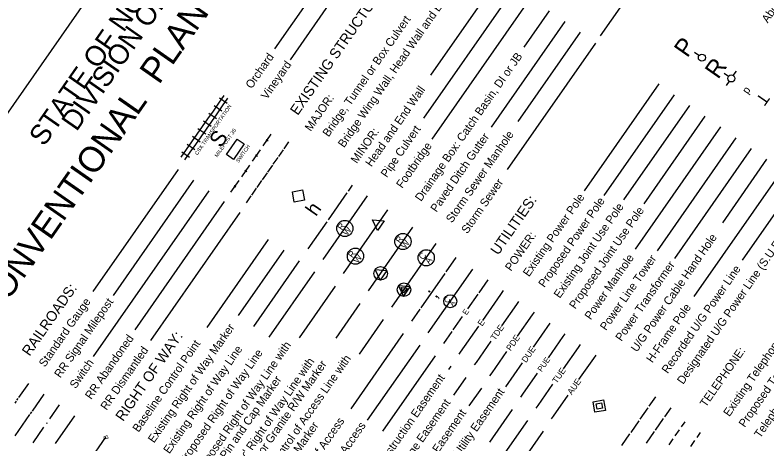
# Model space of a CAD drawing. Extents: x 1731327 to 1735374, y 884856 to 889832.
# Drawn here: x 1733952 to 1734752, y 888724 to 889180 of the extents above; entities that cross this region are included whole.
import ezdxf

# ---------------------------------------------------------------- set-up
doc = ezdxf.new("R2010")
doc.units = 0
for name, color, linetype in [('Exist Building', 7, 'Continuous'), ('Exist Roads EOP Other', 7, 'Continuous'), ('Exist Structure Major Deck Tunnel Box Culvert Text', 7, 'Continuous'), ('Exist Utilities Telephone Pole CELL', 7, 'Continuous'), ('Exist Vegetation Woods Line', 7, 'Continuous')]:
    doc.layers.add(name, color=color, linetype=linetype)

msp = doc.modelspace()

# ---------------------------------------------------------------- linework, layer by layer
at = {"layer": 'Exist Building'}
for p, q in [((1734503.78, 888826.4), (1734521.63, 888851.98)), ((1734474.42, 888784.34), (1734492.33, 888810))]:
    msp.add_line(p, q, dxfattribs=at)
at = {"layer": 'Exist Roads EOP Other'}
msp.add_line((1734573.85, 888763.9), (1734573.85, 888763.9), dxfattribs=at)
for points in [[(1734567.25, 888768.51), (1734578.46, 888770.5), (1734580.45, 888759.29), (1734569.24, 888757.3)], [(1734570.55, 888766.2), (1734576.15, 888767.2), (1734577.15, 888761.6), (1734571.55, 888760.6)]]:
    msp.add_lwpolyline(points, close=True, dxfattribs=at)
at = {"layer": 'Exist Structure Major Deck Tunnel Box Culvert Text'}
msp.add_lwpolyline([(1734249.24, 888980.89), (1734247.31, 888991.77), (1734258.2, 888993.71), (1734260.13, 888982.82)], close=True, dxfattribs=at)
at = {"layer": 'Exist Utilities Telephone Pole CELL'}
msp.add_lwpolyline([(1734410.98, 887822.38), (1735374.4, 889202.95), (1734472.34, 889832.45), (1733508.91, 888451.88)], close=True, dxfattribs=at)
msp.add_lwpolyline([(1734410.98, 887822.38), (1735374.4, 889202.95), (1734472.34, 889832.45), (1733508.91, 888451.88)], close=True, dxfattribs=at)
at = {"layer": 'Exist Vegetation Woods Line'}
for p, q in [((1734345.68, 889311.65), (1734228.43, 889143.63)), ((1734362.08, 889300.21), (1734244.83, 889132.18)), ((1734467.87, 889221.13), (1734394.46, 889115.94)), ((1734484.26, 889209.68), (1734386.89, 889070.15)), ((1734500.66, 889198.24), (1734395.69, 889047.81)), ((1734520.69, 889184.26), (1734493.69, 889145.56)), ((1734575.21, 889157.56), (1734598.39, 889190.79)), ((1734537.09, 889172.82), (1734458.73, 889060.54)), ((1734553.49, 889161.38), (1734487.3, 889066.54)), ((1734569.89, 889149.93), (1734475.94, 889015.31)), ((1734679.9, 889136.57), (1734675.29, 889139.79)), ((1734716.44, 889115.38), (1734719.66, 889120)), ((1734711.22, 889114.46), (1734706.61, 889117.67)), ((1734637.07, 889106.45), (1734557.71, 888992.73)), ((1734712.15, 889109.24), (1734708.93, 889104.62)), ((1734168.99, 889085.87), (1734174.71, 889094.07)), ((1734178, 889085.68), (1734169.8, 889091.4)), ((1734173.09, 889083.01), (1734178.81, 889091.21)), ((1734653.47, 889095), (1734578.57, 888987.67)), ((1734163.27, 889077.67), (1734168.99, 889085.87)), ((1734172.28, 889077.48), (1734164.08, 889083.2)), ((1734167.37, 889074.81), (1734173.09, 889083.01)), ((1734669.87, 889083.56), (1734599.77, 888983.11)), ((1734157.55, 889069.47), (1734163.27, 889077.67)), ((1734166.56, 889069.28), (1734158.36, 889075)), ((1734161.65, 889066.61), (1734167.37, 889074.81)), ((1734686.27, 889072.12), (1734621.32, 888979.05)), ((1734151.83, 889061.28), (1734157.55, 889069.47)), ((1734160.84, 889061.08), (1734152.64, 889066.81)), ((1734155.93, 889058.41), (1734161.65, 889066.61)), ((1734146.11, 889053.08), (1734151.83, 889061.28)), ((1734155.12, 889052.88), (1734146.92, 889058.61)), ((1734150.21, 889050.22), (1734155.93, 889058.41)), ((1734702.66, 889060.67), (1734611.98, 888930.72)), ((1734140.38, 889044.88), (1734146.11, 889053.08)), ((1734149.39, 889044.69), (1734141.2, 889050.41)), ((1734144.48, 889042.02), (1734150.21, 889050.22)), ((1734216.37, 889040.62), (1734224.95, 889052.92)), ((1734219.64, 889047.48), (1734221.69, 889046.05)), ((1734719.06, 889049.23), (1734635.24, 888929.12)), ((1734134.66, 889036.68), (1734140.38, 889044.88)), ((1734143.67, 889036.49), (1734135.47, 889042.21)), ((1734138.76, 889033.82), (1734144.48, 889042.02)), ((1734238.49, 889037.37), (1734243.64, 889044.75)), ((1734128.94, 889028.48), (1734134.66, 889036.68)), ((1734137.95, 889028.29), (1734129.75, 889034.01)), ((1734133.04, 889025.62), (1734138.76, 889033.82)), ((1734204.93, 889024.22), (1734213.51, 889036.52)), ((1734232.77, 889029.18), (1734237.92, 889036.55)), ((1734735.46, 889037.79), (1734653.7, 888920.63)), ((1734208.19, 889031.09), (1734210.24, 889029.66)), ((1734227.05, 889020.98), (1734232.19, 889028.36)), ((1734751.86, 889026.35), (1734704.75, 888958.85)), ((1734125.76, 889015.59), (1734035.12, 888885.71)), ((1734193.48, 889007.82), (1734202.07, 889020.12)), ((1734221.32, 889012.78), (1734226.47, 889020.16)), ((1734196.75, 889014.69), (1734198.8, 889013.26)), ((1734215.6, 889004.58), (1734220.75, 889011.96)), ((1734768.25, 889014.9), (1734674.48, 888880.52)), ((1734142.15, 889004.15), (1734056.59, 888881.54)), ((1734182.04, 888991.43), (1734190.62, 889003.72)), ((1734209.88, 888996.38), (1734215.03, 889003.76)), ((1734784.65, 889003.46), (1734725.74, 888919.04)), ((1734158.55, 888992.71), (1734035.59, 888816.5)), ((1734185.31, 888998.29), (1734187.36, 888996.86)), ((1734204.16, 888988.18), (1734209.31, 888995.56)), ((1734307.09, 888992.55), (1734311.38, 888998.7)), ((1734198.44, 888979.98), (1734203.59, 888987.36)), ((1734280.21, 888919.87), (1734327.41, 888987.51)), ((1734285.63, 888961.8), (1734305.66, 888990.5)), ((1734174.95, 888981.26), (1734079.88, 888845.03)), ((1734191.35, 888969.82), (1734096.28, 888833.59)), ((1734191.35, 888969.82), (1734096.28, 888833.59)), ((1734301.63, 888904.93), (1734348.83, 888972.57)), ((1734264.18, 888931.06), (1734284.2, 888959.75)), ((1734328.27, 888886.33), (1734375.47, 888953.97)), ((1734338.5, 888957.77), (1734338.5, 888957.77)), ((1734221.74, 888941.13), (1734156.39, 888847.49)), ((1734353.07, 888869.03), (1734400.27, 888936.67)), ((1734238.14, 888929.69), (1734189.54, 888860.05)), ((1734411, 888906.47), (1734421.66, 888921.74)), ((1734254.53, 888918.24), (1734205.94, 888848.61)), ((1734270.93, 888906.8), (1734222.33, 888837.16)), ((1734341.26, 888904.94), (1734341.26, 888904.94)), ((1734384.45, 888868.42), (1734409.86, 888904.83)), ((1734391.96, 888841.89), (1734439.16, 888909.53)), ((1734445.98, 888884.36), (1734455.56, 888898.09)), ((1734292.95, 888891.44), (1734254.55, 888836.41)), ((1734366.06, 888887.64), (1734366.06, 888887.64)), ((1734434.11, 888867.35), (1734444.84, 888882.72)), ((1734449.85, 888854.96), (1734469.16, 888882.63)), ((1734469.16, 888882.63), (1734471.96, 888886.64)), ((1734319.21, 888873.11), (1734293.47, 888836.22)), ((1734470.25, 888849.25), (1734485.98, 888871.8)), ((1734485.98, 888871.8), (1734488.36, 888875.2)), ((1734374.45, 888854.1), (1734383.3, 888866.78)), ((1734502.64, 888860.72), (1734504.75, 888863.76)), ((1734344.01, 888855.8), (1734318.48, 888819.22)), ((1734418.38, 888844.8), (1734428.39, 888859.15)), ((1734486.9, 888838.18), (1734502.64, 888860.72)), ((1734426.25, 888821.14), (1734445.56, 888848.81)), ((1734365.28, 888840.96), (1734309.47, 888760.98)), ((1734408.36, 888830.44), (1734417.23, 888843.16)), ((1734535.46, 888837.86), (1734537.56, 888840.86)), ((1734443.07, 888810.3), (1734458.8, 888832.85)), ((1734519.73, 888815.31), (1734535.46, 888837.86)), ((1734382.79, 888828.74), (1734326.97, 888748.76)), ((1734535.85, 888803.47), (1734551.58, 888826.02)), ((1734551.58, 888826.02), (1734553.95, 888829.42)), ((1734399.18, 888817.3), (1734343.37, 888737.32)), ((1734424.75, 888819), (1734426.25, 888821.14)), ((1734459.72, 888799.23), (1734475.46, 888821.78)), ((1734567.98, 888814.58), (1734570.35, 888817.98)), ((1734441.15, 888807.56), (1734443.07, 888810.3)), ((1734552.24, 888792.03), (1734567.98, 888814.58)), ((1734415.8, 888806.17), (1734413.41, 888802.75)), ((1734431.98, 888794.42), (1734418.74, 888775.43)), ((1734457.55, 888796.11), (1734459.72, 888799.23)), ((1734492.55, 888776.37), (1734508.28, 888798.92)), ((1733956.36, 888772.85), (1733966.92, 888787.98)), ((1734508.67, 888764.53), (1734524.4, 888787.07)), ((1733970.8, 888758.61), (1733983.31, 888776.53)), ((1734448.38, 888782.97), (1734435.13, 888763.99)), ((1734490.35, 888773.22), (1734492.55, 888776.37)), ((1734525.07, 888753.08), (1734540.8, 888775.63)), ((1733952.35, 888767.11), (1733953.78, 888769.16)), ((1733954.36, 888769.98), (1733955.79, 888772.03)), ((1734627.07, 888763.77), (1734633.94, 888773.61)), ((1733989.41, 888750.33), (1733999.71, 888765.09)), ((1734481.18, 888760.08), (1734457.07, 888725.53)), ((1734506.75, 888761.78), (1734508.67, 888764.53)), ((1734617.35, 888749.83), (1734625.93, 888762.13)), ((1734643.47, 888752.32), (1734650.34, 888762.16)), ((1733952.5, 888732.37), (1733968.23, 888754.92)), ((1733968.8, 888755.74), (1733970.23, 888757.79)), ((1733995.37, 888723.93), (1734016.11, 888753.65)), ((1734523.15, 888750.34), (1734525.07, 888753.08)), ((1733985.98, 888745.41), (1733986.55, 888746.23)), ((1734497.58, 888748.64), (1734473.47, 888714.09)), ((1734607.62, 888735.89), (1734616.2, 888748.19)), ((1734633.74, 888738.39), (1734642.33, 888750.68)), ((1734664.75, 888747.04), (1734661.09, 888741.8)), ((1733971.68, 888724.92), (1733983.12, 888741.31)), ((1734513.98, 888737.19), (1734474.81, 888681.07)), ((1734624.02, 888724.45), (1734632.6, 888736.75)), ((1734658.86, 888738.6), (1734654.36, 888732.16)), ((1734681.15, 888735.6), (1734677.48, 888730.35)), ((1734028.16, 888701.04), (1734048.9, 888730.76)), ((1734597.89, 888721.95), (1734606.47, 888734.25)), ((1734652.25, 888729.13), (1734647.81, 888722.78)), ((1734675.25, 888727.16), (1734670.76, 888720.72))]:
    msp.add_line(p, q, dxfattribs=at)
for points in [[(1734177.1, 889031.45), (1734188.54, 889047.85), (1734196, 889042.64), (1734184.56, 889026.24)], [(1734337.88, 888950.58), (1734332.6, 888961.89), (1734345.03, 888960.83)], [(1734340.64, 888897.76), (1734335.36, 888909.06), (1734347.79, 888908.01)], [(1734365.43, 888880.45), (1734372.59, 888890.7), (1734360.15, 888891.76)], [(1734365.73, 888883.88), (1734362.97, 888889.79), (1734369.47, 888889.24)]]:
    msp.add_lwpolyline(points, close=True, dxfattribs=at)
for centre, radius in [((1734682.98, 889134.43), 3.75), ((1734714.31, 889112.3), 3.75), ((1734303.16, 888952.77), 8.61), ((1734364.94, 888938.88), 8.61), ((1734314.45, 888923.31), 8.61), ((1734389.74, 888921.58), 8.61), ((1734341.26, 888904.94), 7.2), ((1734366.06, 888887.63), 7.2), ((1734415.35, 888875.4), 6.89)]:
    msp.add_circle(centre, radius, dxfattribs=at)

# ---------------------------------------------------------------- texts
at = {"layer": 'Exist Building'}
msp.add_text('DUE', height=6.549, rotation=55.09106, dxfattribs=at).set_placement((1734495.95, 888809.42))
at = {"layer": 'Exist Vegetation Woods Line'}
for s, height, rotation, p in [('CONVENTIONAL  PLAN SHEET SYMBOLS', 27.1947, 55.09106, (1733929.61, 888853.02)), ('STATE OF NORTH CAROLINA', 21.4145, 55.09106, (1733983.25, 889039.08)), ('DIVISION OF HIGHWAYS', 21.4145, 55.09106, (1734017.76, 889055.04)), ('Above Ground Gas Line', 8.7482, 55.09106, (1734753.02, 889170.66)), ('Bridge Wing Wall, Head Wall and End Wall', 8.7482, 55.09106, (1734302.28, 889038.03)), ('EXISTING STRUCTURES:', 10.9977, 55.09106, (1734253.08, 889072.36)), ('Bridge, Tunnel or Box Culvert', 8.7482, 55.09106, (1734285.88, 889049.48)), ('P', 18.75, 55.09106, (1734667.44, 889133.58)), ('Orchard', 8.748, 55.09106, (1734203.97, 889100.68)), ('Drainage Box: Catch Basin, DI or JB', 8.7482, 55.09106, (1734384.26, 888980.83)), ('Vineyard', 8.748, 55.09106, (1734220.37, 889089.23)), ('R', 18.75, 55.09106, (1734700.23, 889110.7)), ('Head and End Wall', 8.7482, 55.09106, (1734331.44, 889017.68)), ('p', 8.25, 55.09106, (1734731.73, 889095.12)), ('MAJOR:', 8.748, 55.09106, (1734266.95, 889055.34)), ('T', 12.5, 235.09108, (1734745.56, 889098.12)), ('CSX TRANSPORTATION', 3.9991, 55.09106, (1734146.41, 889030.39)), ('S', 16.5, 55.09106, (1734171.21, 889037.71)), ('MILEPOST 35', 3.9991, 55.09106, (1734167.47, 889028.11)), ('MINOR:', 8.748, 55.09106, (1734315.89, 889021.18)), ('Pipe Culvert', 8.7482, 55.09106, (1734347.83, 889006.25)), ('Storm Sewer Manhole', 8.7482, 55.09106, (1734417.07, 888957.94)), ('Paved Ditch Gutter', 8.7482, 55.09106, (1734400.67, 888969.38)), ('SWITCH', 3.999, 55.09106, (1734190.2, 889022.25)), ('Footbridge', 8.748, 55.09106, (1734364.23, 888994.81)), ('Storm Sewer', 8.7482, 55.09106, (1734433.47, 888946.5)), ('UTILITIES:', 10.998, 55.09106, (1734466.26, 888923.6)), ('Existing Power Pole', 8.7482, 55.09106, (1734499.05, 888900.73)), ('Proposed Power Pole', 8.7482, 55.09106, (1734515.45, 888889.29)), ('h', 15, 55.09106, (1734272.53, 888964.87)), ('Existing Joint Use Pole', 8.7482, 55.09106, (1734531.83, 888877.85)), ('Proposed Joint Use Pole', 8.7482, 55.09106, (1734548.25, 888866.41)), ('R', 6.75, 55.09106, (1734300.21, 888950.31)), ('W', 6.75, 55.09106, (1734305.85, 888944.5)), ('R', 6.75, 55.09106, (1734361.99, 888936.42)), ('POWER:', 8.748, 55.09106, (1734480.02, 888906.65)), ('U/G Power Cable Hand Hole', 8.7482, 55.09106, (1734613.85, 888820.65)), ('Designated U/G Power Line (S.U.E.*)', 8.7482, 55.09106, (1734663.04, 888786.34)), ('W', 6.75, 55.09106, (1734367.63, 888930.61)), ('R', 6.75, 55.09106, (1734311.5, 888920.85)), ('W', 6.75, 55.09106, (1734317.14, 888915.04)), ('C', 6.75, 55.09106, (1734386.65, 888918.91)), ('A', 6.75, 55.09106, (1734393.13, 888914.31)), ('Power Manhole', 8.7482, 55.09106, (1734564.65, 888854.97)), ('Power Line Tower', 8.7482, 55.09106, (1734581.03, 888843.53)), ('Power Transformer', 8.7482, 55.09106, (1734597.42, 888832.08)), ('Recorded U/G Power Line', 8.7482, 55.09106, (1734646.64, 888797.77)), ('RAILROADS:', 10.998, 55.09106, (1733967.83, 888816.27)), (';', 15, 55.09106, (1734399.91, 888877.48)), ('Standard Gauge', 8.7482, 55.09106, (1733984.05, 888804.62)), ('RR Signal Milepost', 8.7482, 55.09106, (1734000.44, 888793.18)), ('C', 5.4, 55.09106, (1734412.58, 888872.86)), ('A', 5.4, 55.09106, (1734418.21, 888869.59)), ('H-Frame Pole', 8.7482, 55.09106, (1734630.24, 888809.21)), ('E', 6, 55.09106, (1734432.68, 888860.06)), ('E', 6.55, 55.09106, (1734449.18, 888848.24)), ('Existing Telephone Pole', 8.7482, 55.09106, (1734712.23, 888751.99)), ('Existing Right of Way Marker', 8.7482, 55.09106, (1734100.12, 888723.96)), ('TDE', 6.549, 55.09106, (1734463, 888833.1)), ('Proposed Telephone Pole', 8.7482, 55.09106, (1734728.63, 888740.55)), ('RR Abandoned', 8.7482, 55.09106, (1734033.24, 888770.29)), ('RIGHT OF WAY:', 10.9977, 55.09106, (1734067.32, 888746.84)), ('PDE', 6.549, 55.09106, (1734479.59, 888821.94)), ('Baseline Control Point', 8.7482, 55.09106, (1734083.72, 888735.4)), ('Proposed Right of Way Line with', 8.7482, 55.09106, (1734149.31, 888689.63)), ('RR Dismantled', 8.7482, 55.09106, (1734049.64, 888758.85)), ('Existing Right of Way Line', 8.7482, 55.09106, (1734116.51, 888712.51)), ('Proposed Right of Way Line', 8.7482, 55.09106, (1734132.91, 888701.07)), ('TELEPHONE:', 8.748, 55.09106, (1734687.3, 888762)), ('Proposed Control of Access Line with', 8.7482, 55.09106, (1734198.89, 888655.03)), ('PUE', 5.999, 55.09106, (1734512.52, 888799.74)), ('Telephone Manhole', 8.7482, 55.09106, (1734745.03, 888729.11)), ('Switch', 8.748, 55.09106, (1734016.84, 888781.73)), ('Proposed Right of Way Line with', 8.7482, 55.09106, (1734174.09, 888672.33)), ('  Concrete or Granite R/W Marker', 8.7482, 55.09106, (1734184.34, 888665.18)), ('TUE', 6.549, 55.09106, (1734528.58, 888787.3)), ('  Iron Pin and Cap Marker', 8.7482, 55.09106, (1734159.56, 888682.48)), ('Proposed Temporary Construction Easement', 8.7482, 55.09106, (1734275.69, 888601.44)), ('AUE', 6.549, 55.09106, (1734544.61, 888775.32)), ('Proposed Permanent Drainage /  Utility Easement', 8.7482, 55.09106, (1734325.36, 888566.77)), ('Proposed Temporary Drainage Easement', 8.7482, 55.09106, (1734292.08, 888589.99)), ('Proposed Permanent Drainage Easement', 8.7482, 55.09106, (1734308.48, 888578.55)), ('  Concrete C/A Marker', 8.7482, 55.09106, (1734209.14, 888647.88)), ('Existing Control of Access', 8.7482, 55.09106, (1734225.39, 888636.54)), ('Proposed Control of Access', 8.7482, 55.09106, (1734242.89, 888624.32)), ('B', 5, 100.09116, (1734051.8, 888728.74))]:
    msp.add_text(s, height=height, rotation=rotation, dxfattribs=at).set_placement(p)

doc.saveas('drawing.dxf')
